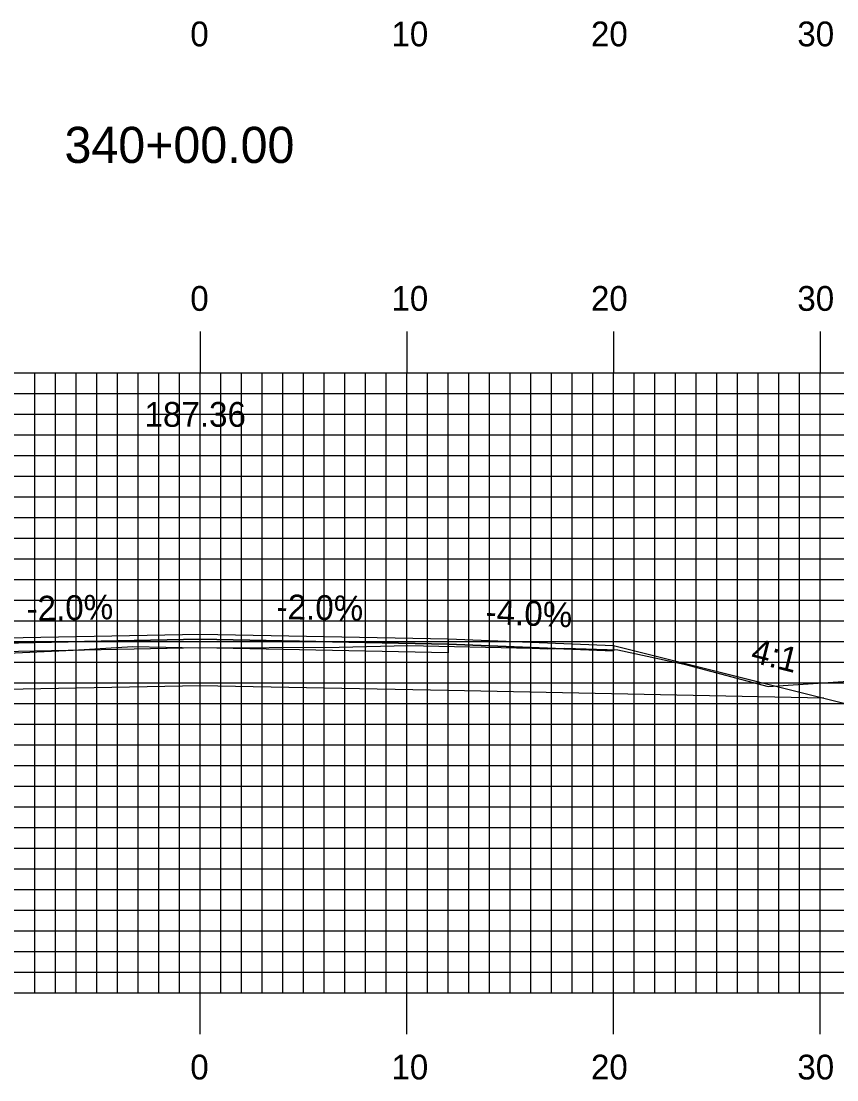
# Model space of a CAD drawing. Extents: x 1824360 to 1824703, y 442591 to 442811.
# Drawn here: x 1824516.7 to 1824556.1, y 442649.4 to 442700.7 of the extents above; entities that cross this region are included whole.
import ezdxf

# ---------------------------------------------------------------- set-up
doc = ezdxf.new("R2010")
doc.units = 0
for name, color, linetype in [('ANNOTATION', 7, 'Continuous'), ('D_Roadway_Centerline', 7, 'Continuous'), ('D_Roadway_Centerline_Text', 7, 'Continuous'), ('D_Roadway_Edge_Shoulder', 7, 'Continuous'), ('D_Roadway_Edge_TW', 7, 'Continuous'), ('D_Roadway_Pavement', 7, 'Continuous'), ('D_Roadway_SlopeLines', 7, 'Continuous'), ('D_Roadway_SubGrade', 7, 'Continuous'), ('H_V ANNOTATION', 7, 'Continuous'), ('MAJOR', 7, 'Continuous'), ('MINOR', 7, 'Continuous'), ('S_Roadway_Centerline', 7, 'Continuous')]:
    doc.layers.add(name, color=color, linetype=linetype)

msp = doc.modelspace()

# ---------------------------------------------------------------- linework, layer by layer
at = {"layer": 'D_Roadway_Centerline'}
msp.add_lwpolyline([(1824495.161, 442667.919), (1824500.073, 442669.147), (1824505.335, 442670.463), (1824513.335, 442670.783), (1824525.335, 442671.023), (1824537.335, 442670.783), (1824545.335, 442670.463), (1824555.509, 442667.919), (1824559.509, 442666.919), (1824562.472, 442668.401), (1824563.722, 442668.962), (1824564.972, 442669.397), (1824566.222, 442669.704), (1824567.472, 442669.885)], dxfattribs=at)
at = {"layer": 'D_Roadway_Edge_Shoulder'}
msp.add_lwpolyline([(1824537.335, 442670.783), (1824545.335, 442670.463), (1824545.335, 442670.213), (1824537.335, 442670.533)], close=True, dxfattribs=at)
at = {"layer": 'D_Roadway_Edge_TW'}
msp.add_lwpolyline([(1824513.335, 442670.533), (1824513.335, 442670.783), (1824525.335, 442671.023), (1824537.335, 442670.783), (1824537.335, 442670.533), (1824525.335, 442670.773)], close=True, dxfattribs=at)
at = {"layer": 'D_Roadway_Pavement'}
msp.add_lwpolyline([(1824513.335, 442670.116), (1824513.335, 442670.533), (1824525.335, 442670.773), (1824537.335, 442670.533), (1824537.335, 442670.116), (1824525.335, 442670.356)], close=True, dxfattribs=at)
at = {"layer": 'D_Roadway_SlopeLines'}
msp.add_lwpolyline([(1824545.335, 442670.463), (1824559.509, 442666.919)], dxfattribs=at)
at = {"layer": 'D_Roadway_SubGrade'}
msp.add_lwpolyline([(1824513.335, 442668.283), (1824495.161, 442667.919), (1824505.335, 442670.463), (1824505.335, 442670.213), (1824513.335, 442670.533), (1824525.335, 442670.773), (1824537.335, 442670.533), (1824545.335, 442670.213), (1824545.335, 442670.463), (1824555.509, 442667.919), (1824537.335, 442668.283), (1824525.335, 442668.523)], close=True, dxfattribs=at)
at = {"layer": 'MAJOR'}
for p, q in [((1824525.335, 442685.669), (1824525.335, 442683.665)), ((1824535.335, 442685.669), (1824535.335, 442683.665)), ((1824545.335, 442685.669), (1824545.335, 442683.665)), ((1824555.335, 442685.669), (1824555.335, 442683.665)), ((1824385.335, 442683.665), (1824665.335, 442683.665)), ((1824385.335, 442683.665), (1824665.335, 442683.665)), ((1824525.335, 442653.665), (1824525.335, 442683.665)), ((1824535.335, 442653.665), (1824535.335, 442683.665)), ((1824545.335, 442653.665), (1824545.335, 442683.665)), ((1824555.335, 442653.665), (1824555.335, 442683.665)), ((1824385.335, 442678.665), (1824665.335, 442678.665)), ((1824385.335, 442673.665), (1824665.335, 442673.665)), ((1824385.335, 442668.665), (1824665.335, 442668.665)), ((1824385.335, 442663.665), (1824665.335, 442663.665)), ((1824385.335, 442658.665), (1824665.335, 442658.665)), ((1824385.335, 442653.665), (1824665.335, 442653.665)), ((1824385.335, 442653.665), (1824665.335, 442653.665)), ((1824525.335, 442651.661), (1824525.335, 442653.665)), ((1824535.335, 442651.661), (1824535.335, 442653.665)), ((1824545.335, 442651.661), (1824545.335, 442653.665)), ((1824555.335, 442651.661), (1824555.335, 442653.665))]:
    msp.add_line(p, q, dxfattribs=at)
at = {"layer": 'MINOR'}
for p, q in [((1824517.335, 442653.665), (1824517.335, 442683.665)), ((1824518.335, 442653.665), (1824518.335, 442683.665)), ((1824519.335, 442653.665), (1824519.335, 442683.665)), ((1824520.335, 442653.665), (1824520.335, 442683.665)), ((1824521.335, 442653.665), (1824521.335, 442683.665)), ((1824522.335, 442653.665), (1824522.335, 442683.665)), ((1824523.335, 442653.665), (1824523.335, 442683.665)), ((1824524.335, 442653.665), (1824524.335, 442683.665)), ((1824526.335, 442653.665), (1824526.335, 442683.665)), ((1824527.335, 442653.665), (1824527.335, 442683.665)), ((1824528.335, 442653.665), (1824528.335, 442683.665)), ((1824529.335, 442653.665), (1824529.335, 442683.665)), ((1824530.335, 442653.665), (1824530.335, 442683.665)), ((1824531.335, 442653.665), (1824531.335, 442683.665)), ((1824532.335, 442653.665), (1824532.335, 442683.665)), ((1824533.335, 442653.665), (1824533.335, 442683.665)), ((1824534.335, 442653.665), (1824534.335, 442683.665)), ((1824536.335, 442653.665), (1824536.335, 442683.665)), ((1824537.335, 442653.665), (1824537.335, 442683.665)), ((1824538.335, 442653.665), (1824538.335, 442683.665)), ((1824539.335, 442653.665), (1824539.335, 442683.665)), ((1824540.335, 442653.665), (1824540.335, 442683.665)), ((1824541.335, 442653.665), (1824541.335, 442683.665)), ((1824542.335, 442653.665), (1824542.335, 442683.665)), ((1824543.335, 442653.665), (1824543.335, 442683.665)), ((1824544.335, 442653.665), (1824544.335, 442683.665)), ((1824546.335, 442653.665), (1824546.335, 442683.665)), ((1824547.335, 442653.665), (1824547.335, 442683.665)), ((1824548.335, 442653.665), (1824548.335, 442683.665)), ((1824549.335, 442653.665), (1824549.335, 442683.665)), ((1824550.335, 442653.665), (1824550.335, 442683.665)), ((1824551.335, 442653.665), (1824551.335, 442683.665)), ((1824552.335, 442653.665), (1824552.335, 442683.665)), ((1824553.335, 442653.665), (1824553.335, 442683.665)), ((1824554.335, 442653.665), (1824554.335, 442683.665)), ((1824385.335, 442682.665), (1824665.335, 442682.665)), ((1824385.335, 442681.665), (1824665.335, 442681.665)), ((1824385.335, 442680.665), (1824665.335, 442680.665)), ((1824385.335, 442679.665), (1824665.335, 442679.665)), ((1824385.335, 442677.665), (1824665.335, 442677.665)), ((1824385.335, 442676.665), (1824665.335, 442676.665)), ((1824385.335, 442675.665), (1824665.335, 442675.665)), ((1824385.335, 442674.665), (1824665.335, 442674.665)), ((1824385.335, 442672.665), (1824665.335, 442672.665)), ((1824385.335, 442671.665), (1824665.335, 442671.665)), ((1824385.335, 442670.665), (1824665.335, 442670.665)), ((1824385.335, 442669.665), (1824665.335, 442669.665)), ((1824385.335, 442667.665), (1824665.335, 442667.665)), ((1824385.335, 442666.665), (1824665.335, 442666.665)), ((1824385.335, 442665.665), (1824665.335, 442665.665)), ((1824385.335, 442664.665), (1824665.335, 442664.665)), ((1824385.335, 442662.665), (1824665.335, 442662.665)), ((1824385.335, 442661.665), (1824665.335, 442661.665)), ((1824385.335, 442660.665), (1824665.335, 442660.665)), ((1824385.335, 442659.665), (1824665.335, 442659.665)), ((1824385.335, 442657.665), (1824665.335, 442657.665)), ((1824385.335, 442656.665), (1824665.335, 442656.665)), ((1824385.335, 442655.665), (1824665.335, 442655.665)), ((1824385.335, 442654.665), (1824665.335, 442654.665))]:
    msp.add_line(p, q, dxfattribs=at)
at = {"layer": 'S_Roadway_Centerline'}
msp.add_lwpolyline([(1824510.764, 442669.859), (1824519.18, 442670.249), (1824522.079, 442670.426), (1824525.261, 442670.355), (1824532.064, 442670.384), (1824535.378, 442670.469), (1824541.4, 442670.335), (1824542.121, 442670.312), (1824542.458, 442670.315), (1824542.491, 442670.319), (1824542.977, 442670.338), (1824545.548, 442670.251), (1824548.755, 442669.568), (1824552.816, 442668.477), (1824556.938, 442668.751), (1824559.063, 442668.996), (1824559.273, 442669.03), (1824562.836, 442669.432), (1824565.983, 442669.754), (1824572.676, 442670.341), (1824576.264, 442670.67), (1824591.059, 442672.098), (1824594.234, 442672.354), (1824601.122, 442672.986)], dxfattribs=at)

# ---------------------------------------------------------------- texts
at = {"layer": 'ANNOTATION'}
for s, rotation, p in [('-2.0%', 1.1458, (1824516.941, 442671.655)), ('-2.0%', 358.8542, (1824529.021, 442671.749)), ('-4.0%', 357.7094, (1824539.127, 442671.513)), ('4:1', 345.9638, (1824551.928, 442669.676))]:
    msp.add_text(s, height=1.2, rotation=rotation, dxfattribs=at).set_placement(p)
at = {"layer": 'D_Roadway_Centerline'}
for s, p in [('C', (1824525.33, 442671.023)), ('L', (1824525.335, 442671.015))]:
    msp.add_text(s, height=0.0146, dxfattribs=at).set_placement(p)
at = {"layer": 'D_Roadway_Centerline_Text'}
msp.add_text('187.36', height=1.2, dxfattribs=at).set_placement((1824522.638, 442681.053))
at = {"layer": 'H_V ANNOTATION'}
for s, height, p in [('0', 1.2, (1824524.853, 442699.465)), ('10', 1.2, (1824534.586, 442699.465)), ('20', 1.2, (1824544.243, 442699.465)), ('30', 1.2, (1824554.232, 442699.465)), ('340+00.00', 1.75, (1824518.765, 442693.821)), ('0', 1.2, (1824524.853, 442686.665)), ('10', 1.2, (1824534.586, 442686.665)), ('20', 1.2, (1824544.243, 442686.665)), ('30', 1.2, (1824554.232, 442686.665)), ('0', 1.2, (1824524.853, 442649.465)), ('10', 1.2, (1824534.586, 442649.465)), ('20', 1.2, (1824544.243, 442649.465)), ('30', 1.2, (1824554.232, 442649.465))]:
    msp.add_text(s, height=height, dxfattribs=at).set_placement(p)
at = {"layer": 'S_Roadway_Centerline'}
for s, p in [('L', (1824522.071, 442670.419)), ('C', (1824522.074, 442670.426))]:
    msp.add_text(s, height=0.0146, dxfattribs=at).set_placement(p)

doc.saveas('drawing.dxf')
